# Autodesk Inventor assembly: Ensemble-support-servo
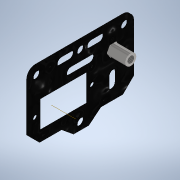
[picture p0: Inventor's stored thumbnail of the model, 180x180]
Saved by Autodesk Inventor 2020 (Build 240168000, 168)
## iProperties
Created: 2021-10
Part Number: Ensemble-support-servo
Document SubType Name: Assembly
Designer: bruno
Author: bruno
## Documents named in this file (3)
- C:\Users\bruno\Documents\1-Cours-2021-22\1SI\Challenge-2021\Pince-Inventor\Ensemble-support-servo.iam
- C:\Users\bruno\Documents\1-Cours-2021-22\1SI\Challenge-2021\Pince-Inventor\support-servo.ipt
- C:\Users\bruno\Documents\1-Cours-2021-22\1SI\Challenge-2021\Pince-Inventor\Ecrou-support.ipt
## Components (2 placed, 2 different names)
1. support-servo:1 — Placage:1, Placage:2, Affleurement:1
2. Ecrou-support:1 — Placage:1, Placage:2, Affleurement:1
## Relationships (3: Mate 2, Flush 1)
- Placage:1 [Mate]: support-servo:1 ↔ Ecrou-support:1
- Placage:2 [Mate]: support-servo:1 ↔ Ecrou-support:1
- Affleurement:1 [Flush]: support-servo:1 ↔ Ecrou-support:1
